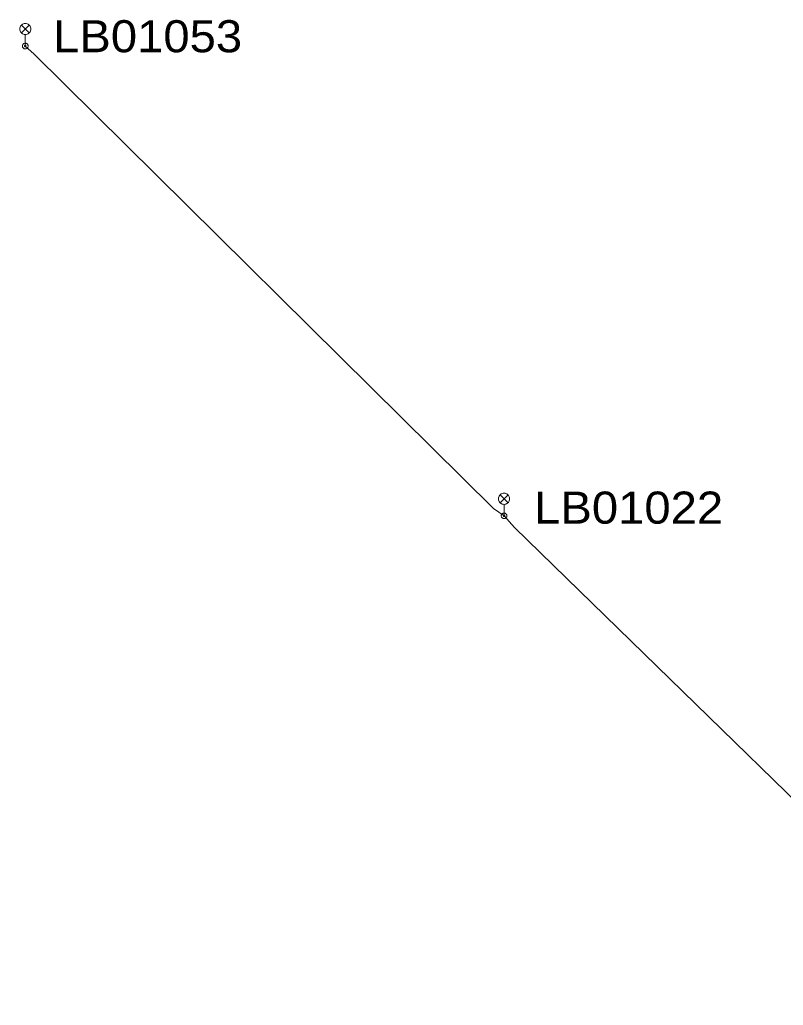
# Model space of a CAD drawing. Extents: x -688049 to -687261, y -973611 to -973038.
# Drawn here: x -687480.1 to -687428.6, y -973170.9 to -973104.4 of the extents above; entities that cross this region are included whole.
import ezdxf

# ---------------------------------------------------------------- set-up
doc = ezdxf.new("R2010")
doc.units = 0
doc.header["$LTSCALE"] = 0.87
doc.layers.add('1', color=7, linetype='Continuous', lineweight=13)

msp = doc.modelspace()

# ---------------------------------------------------------------- linework, layer by layer
at = {"layer": '1'}
for p, q in [((-687480.015, -973104.735), (-687479.485, -973105.265)), ((-687480.015, -973105.265), (-687479.485, -973104.735)), ((-687479.75, -973106.15), (-687479.75, -973105.375)), ((-687447.685, -973136.455), (-687447.155, -973136.985)), ((-687447.685, -973136.985), (-687447.155, -973136.455)), ((-687447.42, -973137.87), (-687447.42, -973137.095))]:
    msp.add_line(p, q, dxfattribs=at)
for points in [[(-687479.375, -973105), (-687479.381, -973104.935), (-687479.398, -973104.872), (-687479.425, -973104.812), (-687479.463, -973104.759), (-687479.509, -973104.713), (-687479.562, -973104.675), (-687479.622, -973104.648), (-687479.685, -973104.631), (-687479.75, -973104.625), (-687479.815, -973104.631), (-687479.878, -973104.648), (-687479.938, -973104.675), (-687479.991, -973104.713), (-687480.037, -973104.759), (-687480.075, -973104.812), (-687480.102, -973104.872), (-687480.119, -973104.935), (-687480.125, -973105), (-687480.119, -973105.065), (-687480.102, -973105.128), (-687480.075, -973105.188), (-687480.037, -973105.241), (-687479.991, -973105.287), (-687479.938, -973105.325), (-687479.878, -973105.352), (-687479.815, -973105.369), (-687479.75, -973105.375), (-687479.685, -973105.369), (-687479.622, -973105.352), (-687479.562, -973105.325), (-687479.509, -973105.287), (-687479.463, -973105.241), (-687479.425, -973105.188), (-687479.398, -973105.128), (-687479.381, -973105.065)], [(-687479.56, -973106.15), (-687479.563, -973106.117), (-687479.571, -973106.085), (-687479.585, -973106.055), (-687479.604, -973106.028), (-687479.628, -973106.004), (-687479.655, -973105.985), (-687479.685, -973105.971), (-687479.717, -973105.963), (-687479.75, -973105.96), (-687479.783, -973105.963), (-687479.815, -973105.971), (-687479.845, -973105.985), (-687479.872, -973106.004), (-687479.896, -973106.028), (-687479.915, -973106.055), (-687479.929, -973106.085), (-687479.937, -973106.117), (-687479.94, -973106.15), (-687479.937, -973106.183), (-687479.929, -973106.215), (-687479.915, -973106.245), (-687479.896, -973106.272), (-687479.872, -973106.296), (-687479.845, -973106.315), (-687479.815, -973106.329), (-687479.783, -973106.337), (-687479.75, -973106.34), (-687479.717, -973106.337), (-687479.685, -973106.329), (-687479.655, -973106.315), (-687479.628, -973106.296), (-687479.604, -973106.272), (-687479.585, -973106.245), (-687479.571, -973106.215), (-687479.563, -973106.183)], [(-687479.7, -973106.15), (-687479.701, -973106.141), (-687479.703, -973106.133), (-687479.707, -973106.125), (-687479.712, -973106.118), (-687479.718, -973106.112), (-687479.725, -973106.107), (-687479.733, -973106.103), (-687479.741, -973106.101), (-687479.75, -973106.1), (-687479.759, -973106.101), (-687479.767, -973106.103), (-687479.775, -973106.107), (-687479.782, -973106.112), (-687479.788, -973106.118), (-687479.793, -973106.125), (-687479.797, -973106.133), (-687479.799, -973106.141), (-687479.8, -973106.15), (-687479.799, -973106.159), (-687479.797, -973106.167), (-687479.793, -973106.175), (-687479.788, -973106.182), (-687479.782, -973106.188), (-687479.775, -973106.193), (-687479.767, -973106.197), (-687479.759, -973106.199), (-687479.75, -973106.2), (-687479.741, -973106.199), (-687479.733, -973106.197), (-687479.725, -973106.193), (-687479.718, -973106.188), (-687479.712, -973106.182), (-687479.707, -973106.175), (-687479.703, -973106.167), (-687479.701, -973106.159)], [(-687447.045, -973136.72), (-687447.051, -973136.655), (-687447.068, -973136.592), (-687447.095, -973136.533), (-687447.133, -973136.479), (-687447.179, -973136.433), (-687447.232, -973136.395), (-687447.292, -973136.368), (-687447.355, -973136.351), (-687447.42, -973136.345), (-687447.485, -973136.351), (-687447.548, -973136.368), (-687447.608, -973136.395), (-687447.661, -973136.433), (-687447.707, -973136.479), (-687447.745, -973136.533), (-687447.772, -973136.592), (-687447.789, -973136.655), (-687447.795, -973136.72), (-687447.789, -973136.785), (-687447.772, -973136.848), (-687447.745, -973136.908), (-687447.707, -973136.961), (-687447.661, -973137.007), (-687447.608, -973137.045), (-687447.548, -973137.072), (-687447.485, -973137.089), (-687447.42, -973137.095), (-687447.355, -973137.089), (-687447.292, -973137.072), (-687447.232, -973137.045), (-687447.179, -973137.007), (-687447.133, -973136.961), (-687447.095, -973136.908), (-687447.068, -973136.848), (-687447.051, -973136.785)], [(-687447.23, -973137.87), (-687447.233, -973137.837), (-687447.241, -973137.805), (-687447.255, -973137.775), (-687447.274, -973137.748), (-687447.298, -973137.724), (-687447.325, -973137.705), (-687447.355, -973137.691), (-687447.387, -973137.683), (-687447.42, -973137.68), (-687447.453, -973137.683), (-687447.485, -973137.691), (-687447.515, -973137.705), (-687447.542, -973137.724), (-687447.566, -973137.748), (-687447.585, -973137.775), (-687447.599, -973137.805), (-687447.607, -973137.837), (-687447.61, -973137.87), (-687447.607, -973137.903), (-687447.599, -973137.935), (-687447.585, -973137.965), (-687447.566, -973137.992), (-687447.542, -973138.016), (-687447.515, -973138.035), (-687447.485, -973138.049), (-687447.453, -973138.057), (-687447.42, -973138.06), (-687447.387, -973138.057), (-687447.355, -973138.049), (-687447.325, -973138.035), (-687447.298, -973138.016), (-687447.274, -973137.992), (-687447.255, -973137.965), (-687447.241, -973137.935), (-687447.233, -973137.903)], [(-687447.37, -973137.87), (-687447.371, -973137.861), (-687447.373, -973137.853), (-687447.377, -973137.845), (-687447.382, -973137.838), (-687447.388, -973137.832), (-687447.395, -973137.827), (-687447.403, -973137.823), (-687447.411, -973137.821), (-687447.42, -973137.82), (-687447.429, -973137.821), (-687447.437, -973137.823), (-687447.445, -973137.827), (-687447.452, -973137.832), (-687447.458, -973137.838), (-687447.463, -973137.845), (-687447.467, -973137.853), (-687447.469, -973137.861), (-687447.47, -973137.87), (-687447.469, -973137.879), (-687447.467, -973137.887), (-687447.463, -973137.895), (-687447.458, -973137.902), (-687447.452, -973137.908), (-687447.445, -973137.913), (-687447.437, -973137.917), (-687447.429, -973137.919), (-687447.42, -973137.92), (-687447.411, -973137.919), (-687447.403, -973137.917), (-687447.395, -973137.913), (-687447.388, -973137.908), (-687447.382, -973137.902), (-687447.377, -973137.895), (-687447.373, -973137.887), (-687447.371, -973137.879)]]:
    msp.add_lwpolyline(points, close=True, dxfattribs=at)
for points in [[(-687479.75, -973106.15), (-687479.182, -973106.673), (-687448.133, -973137.379), (-687447.42, -973137.87)], [(-687447.42, -973137.87), (-687446.715, -973138.656), (-687414.387, -973170.158), (-687413.85, -973170.92)]]:
    msp.add_lwpolyline(points, dxfattribs=at)

# ---------------------------------------------------------------- texts
at = {"layer": '1', "width": 1.1}
for s, p in [('LB01053', (-687477.871, -973106.571)), ('LB01022', (-687445.392, -973138.4))]:
    msp.add_text(s, height=2.167, dxfattribs=at).set_placement(p)

doc.saveas('drawing.dxf')
